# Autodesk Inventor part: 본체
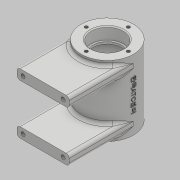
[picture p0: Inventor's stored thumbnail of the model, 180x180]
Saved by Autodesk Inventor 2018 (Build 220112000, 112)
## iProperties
Created: 2020-07
Part Number: 본체
Material: 일반
Document SubType Name: Modeling
Designer: home
Density: 1 g/cm^3
Appearance: 기본값
Author: home
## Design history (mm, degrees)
sketch "스케치1"
  geometry: L1 (16, 35)-(26, 35); L2 (26, 35)-(26, -35); L3 (26, -35)-(16, -35); L4 (16, -35)-(16, -23); L5 (16, -23)-(14, -23); L6 (14, -23)-(14, -21); L7 (21, -21)-(14, -21); L8 (21, -21)-(21, 21); L9 (21, 21)-(14, 21); L10 (14, 21)-(14, 23); L11 (14, 23)-(16, 23); L12 (16, 23)-(16, 35); L13 (0, 76.964)-(0, -76.964); 3 further points
  constraints: 26 end point, 9 perpendicular, 2 midpoint, 2 vertical, 1 coincident, 1 horizontal
  dimensions: "d4" = 10 distance of L1.start L1.end; "d5" = 70 distance of L1.end L2.end; "d6" = 10 distance of L2.end L3.end; "d7" = 12 distance of L3.end L4.end; "d8" = 2 distance of L4.end L5.end; "d9" = 2 distance of L5.end L6.end; "d10" = 42 distance of L7.start L8.end; "d11" = 2 distance of L9.end L10.end; "d12" = 2 distance of L10.end L11.end; "d19" = 35 distance from line of point (0, 0) L1; "d20" = 52 diameter of L2 L13; "d21" = 32 diameter of L12 L13 (derived); "d22" = 42 diameter of L8 L13; "d23" = 111.96433 distance from line of L13.start L3
revolve "회전2" sketch "스케치1" stored, may be unused: angle "d24" = 90 deg
node "작업 평면1"
sketch "스케치2"
  geometry: L1 (0, 0)-(0, 20); L2 (0, 0)-(0, -20); L3 (0, 20)-(26, 20); L4 (26, 20)-(26, 30); L5 (26, 30)-(-26, 30); L6 (-26, 30)-(-26, 20); L7 (0, 20)-(-26, 20)
  constraints: 14 end point, 2 horizontal, 2 perpendicular, 2 vertical, 1 point on line
  dimensions: "d26" = 20 distance of L1.start L1.end; "d27" = 20 distance of L1.start L2.end; "d28" = 26 distance of L1.end L3.end; "d29" = 10 distance of L3.end L4.end; "d30" = 52 distance of L4.end L5.end; "d31" = 10 distance of L5.end L6.end
extrude "돌출1" join sketch "스케치2" stored distance "d32" = 10; taper "d33" = 0 deg
sketch "스케치3"
  geometry: L1 (-26, 20)-(26, 20) reference; L2 (0, 20)-(0, 25); L3 (0, 25)-(20, 25); L4 (0, 25)-(-20, 25); 3 further points
  constraints: 6 end point, 2 coincident, 1 horizontal, 1 midpoint, 1 perpendicular, 1 vertical
  dimensions: "d34" = 5 distance of L2.start L2.end; "d35" = 20 distance of L2.end L3.end; "d36" = 20 distance of L2.end L4.end
hole "구멍1" sketch "스케치3" at (20, 25), (-20, 25) diameter "d37" = 4.134; stored, may be unused: countersink angle "d41" = 90 deg, drill point angle "d43" = 118 deg; dims "d38" = 8, "d39" = 4, "d40" = 2, "d42" = 10
sketch "스케치4"
  geometry: C1 r 21 at (0, 0); 3 further points
  constraints: 1 centre point, 1 coincident, 1 vertical alignment, 2 other
  dimensions: "d44" = 42 diameter of C1
hole "구멍2" sketch "스케치4" at (0, 21) diameter "d45" = 3.242; stored, may be unused: countersink angle "d49" = 90 deg, drill point angle "d51" = 118 deg; dims "d46" = 8, "d47" = 4, "d48" = 2, "d50" = 10
node "작업 평면2"
sketch "스케치5"
  geometry: C1 r 5 at (0, 0); 1 further point
  constraints: 1 centre point, 1 coincident
  dimensions: "d56" = 10 diameter of C1
extrude "돌출2" join sketch "스케치5" stored distance "d57" = 10; taper "d58" = 0 deg
sketch "스케치6"
  geometry: L1 (0, 0)-(0, -40.46); L2 (0, 0)-(-9.919, -27.251); 1 further point
  constraints: 4 end point, 1 coincident, 1 vertical
  dimensions: "d85" = 29 distance of L1.start L2.end; "d86" = 20 deg angle of L1 L2; "d87" = 13.83811 distance from line of L1.end L2
sketch "스케치8"
  geometry: 2 further points
  constraints: 1 coincident
hole "구멍3" sketch "스케치8" at (0, 0) diameter "d65" = 5.188; stored, may be unused: countersink angle "d69" = 90 deg, drill point angle "d71" = 118 deg; dims "d66" = 20, "d67" = 4, "d68" = 2, "d70" = 20
chamfer "모따기1" distance "d82" = 1; stored, may be unused: second distance "d83" = 2, angle "d84" = 45 deg
node "작업 평면4"
sketch "스케치10"
  geometry: C1 r 6 at (0, 0); 1 further point
  constraints: 1 centre point, 1 coincident
  dimensions: "d88" = 12 diameter of C1
extrude "돌출4" join sketch "스케치10" stored distance "d89" = 10; taper "d90" = 0 deg
sketch "스케치11"
  geometry: 2 further points
  constraints: 1 coincident
hole "구멍5" sketch "스케치11" at (0, 0) diameter "d91" = 5.188; stored, may be unused: countersink angle "d95" = 90 deg, drill point angle "d97" = 118 deg; dims "d92" = 20, "d93" = 4, "d94" = 2, "d96" = 20
fillet "모깎기1" dims "d79" = 3, "d80" = 2, "d81" = 3
node "작업 평면5"
sketch "스케치12"
  geometry: L1 (-26, 35)-(26, 35) reference; L2 (29, 5)-(29, -5) reference; 2 further points
  constraints: 1 other
  dimensions: "d99" = 35 distance from line of L1 point (0, 0); "d100" = 29 distance from line of L2 point (0, 0)
feature "엠보싱1" sketch "스케치12" dims "d4" = 10, "d5" = 70, "d6" = 10, "d7" = 12, "d8" = 2, "d9" = 2, "d10" = 42, "d11" = 2, "d12" = 2, "d19" = 35, "d20" = 52, "d21" = 32 (derived), "d22" = 42, "d23" = 111.96433, "d26" = 20, "d28" = 26, "d29" = 10, "d30" = 52, "d31" = 10, "d101" = 0.5, "d102" = 0
node "솔리드2"
pattern_circular "원형 패턴1" dims angle "d53" = 360 deg
mirror "미러1"
other parameters: "d25" = -64, "d55" = 29, "d98" = 26
